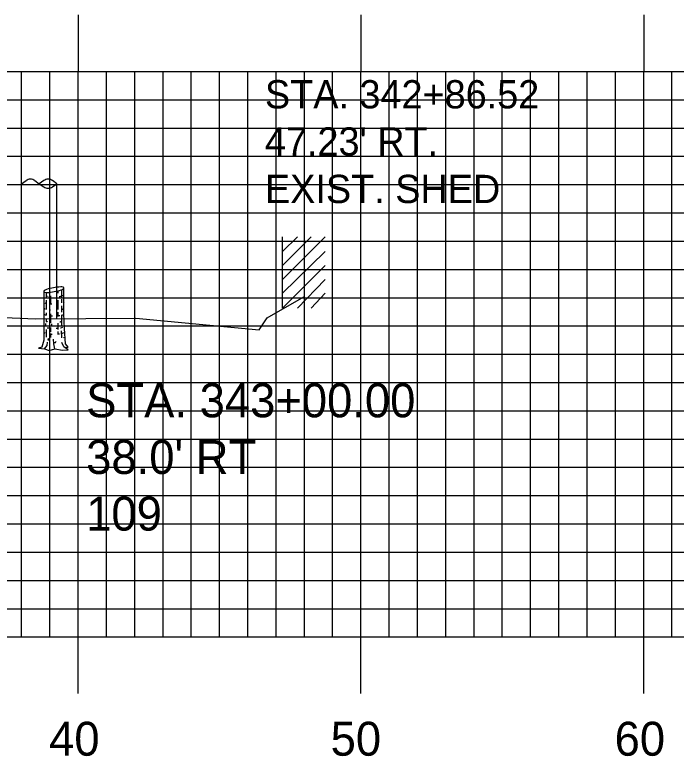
# Model space of a CAD drawing. Extents: x 1825147 to 1825490, y 442591 to 442811.
# Drawn here: x 1825350.12 to 1825373.51, y 442684.45 to 442710.67 of the extents above; entities that cross this region are included whole.
import ezdxf

# ---------------------------------------------------------------- set-up
doc = ezdxf.new("R2010")
doc.units = 0
for name, color, linetype in [('D_Drainage_Text', 7, 'Continuous'), ('D_Text_Monospaced', 7, 'Continuous'), ('D_Utilities_Pole_Joint', 7, 'Continuous'), ('H_V ANNOTATION', 7, 'Continuous'), ('MAJOR', 7, 'Continuous'), ('MINOR', 7, 'Continuous'), ('S_Buildings_SillElevation', 7, 'Continuous'), ('S_Roadway_Centerline', 7, 'Continuous'), ('S_Trees_Conifer_NonPay', 7, 'Continuous')]:
    doc.layers.add(name, color=color, linetype=linetype)

msp = doc.modelspace()

# ---------------------------------------------------------------- linework, layer by layer
at = {"layer": 'D_Utilities_Pole_Joint'}
for p, q in [((1825350.361, 442704.693), (1825350.517, 442704.804)), ((1825350.361, 442699.936), (1825350.361, 442704.693)), ((1825350.83, 442704.804), (1825350.986, 442704.693)), ((1825351.142, 442704.804), (1825350.986, 442704.693)), ((1825350.986, 442704.693), (1825351.142, 442704.582)), ((1825351.611, 442704.693), (1825351.455, 442704.804)), ((1825351.455, 442704.582), (1825351.611, 442704.693)), ((1825351.611, 442699.936), (1825351.611, 442704.693))]:
    msp.add_line(p, q, dxfattribs=at)
for centre, start, end in [((1825350.673, 442704.583), 90, 125.2644), ((1825350.673, 442704.583), 54.7356, 90), ((1825351.298, 442704.583), 90, 125.2644), ((1825351.298, 442704.583), 54.7356, 90), ((1825351.298, 442704.804), 234.7356, 270), ((1825351.298, 442704.804), 270, 305.2644)]:
    msp.add_arc(centre, 0.271, start, end, dxfattribs=at)
at = {"layer": 'MAJOR'}
for p, q in [((1825352.361, 442710.669), (1825352.361, 442708.665)), ((1825362.361, 442710.669), (1825362.361, 442708.665)), ((1825372.361, 442710.669), (1825372.361, 442708.665)), ((1825172.361, 442708.665), (1825452.361, 442708.665)), ((1825172.361, 442708.665), (1825452.361, 442708.665)), ((1825172.361, 442708.665), (1825452.361, 442708.665)), ((1825352.361, 442688.665), (1825352.361, 442708.665)), ((1825352.361, 442688.665), (1825352.361, 442708.665)), ((1825362.361, 442688.665), (1825362.361, 442708.665)), ((1825362.361, 442688.665), (1825362.361, 442708.665)), ((1825372.361, 442688.665), (1825372.361, 442708.665)), ((1825372.361, 442688.665), (1825372.361, 442708.665)), ((1825172.361, 442703.665), (1825452.361, 442703.665)), ((1825172.361, 442703.665), (1825452.361, 442703.665)), ((1825172.361, 442698.665), (1825452.361, 442698.665)), ((1825172.361, 442698.665), (1825452.361, 442698.665)), ((1825172.361, 442693.665), (1825452.361, 442693.665)), ((1825172.361, 442693.665), (1825452.361, 442693.665)), ((1825172.361, 442688.665), (1825452.361, 442688.665)), ((1825172.361, 442688.665), (1825452.361, 442688.665)), ((1825172.361, 442688.665), (1825452.361, 442688.665)), ((1825352.361, 442686.661), (1825352.361, 442688.665)), ((1825362.361, 442686.661), (1825362.361, 442688.665)), ((1825372.361, 442686.661), (1825372.361, 442688.665))]:
    msp.add_line(p, q, dxfattribs=at)
at = {"layer": 'MINOR'}
for p, q in [((1825350.361, 442688.665), (1825350.361, 442708.665)), ((1825350.361, 442688.665), (1825350.361, 442708.665)), ((1825351.361, 442688.665), (1825351.361, 442708.665)), ((1825351.361, 442688.665), (1825351.361, 442708.665)), ((1825353.361, 442688.665), (1825353.361, 442708.665)), ((1825353.361, 442688.665), (1825353.361, 442708.665)), ((1825354.361, 442688.665), (1825354.361, 442708.665)), ((1825354.361, 442688.665), (1825354.361, 442708.665)), ((1825355.361, 442688.665), (1825355.361, 442708.665)), ((1825355.361, 442688.665), (1825355.361, 442708.665)), ((1825356.361, 442688.665), (1825356.361, 442708.665)), ((1825356.361, 442688.665), (1825356.361, 442708.665)), ((1825357.361, 442688.665), (1825357.361, 442708.665)), ((1825357.361, 442688.665), (1825357.361, 442708.665)), ((1825358.361, 442688.665), (1825358.361, 442708.665)), ((1825358.361, 442688.665), (1825358.361, 442708.665)), ((1825359.361, 442688.665), (1825359.361, 442708.665)), ((1825359.361, 442688.665), (1825359.361, 442708.665)), ((1825360.361, 442688.665), (1825360.361, 442708.665)), ((1825360.361, 442688.665), (1825360.361, 442708.665)), ((1825361.361, 442688.665), (1825361.361, 442708.665)), ((1825361.361, 442688.665), (1825361.361, 442708.665)), ((1825363.361, 442688.665), (1825363.361, 442708.665)), ((1825363.361, 442688.665), (1825363.361, 442708.665)), ((1825364.361, 442688.665), (1825364.361, 442708.665)), ((1825364.361, 442688.665), (1825364.361, 442708.665)), ((1825365.361, 442688.665), (1825365.361, 442708.665)), ((1825365.361, 442688.665), (1825365.361, 442708.665)), ((1825366.361, 442688.665), (1825366.361, 442708.665)), ((1825366.361, 442688.665), (1825366.361, 442708.665)), ((1825367.361, 442688.665), (1825367.361, 442708.665)), ((1825367.361, 442688.665), (1825367.361, 442708.665)), ((1825368.361, 442688.665), (1825368.361, 442708.665)), ((1825368.361, 442688.665), (1825368.361, 442708.665)), ((1825369.361, 442688.665), (1825369.361, 442708.665)), ((1825369.361, 442688.665), (1825369.361, 442708.665)), ((1825370.361, 442688.665), (1825370.361, 442708.665)), ((1825370.361, 442688.665), (1825370.361, 442708.665)), ((1825371.361, 442688.665), (1825371.361, 442708.665)), ((1825371.361, 442688.665), (1825371.361, 442708.665)), ((1825373.361, 442688.665), (1825373.361, 442708.665)), ((1825373.361, 442688.665), (1825373.361, 442708.665)), ((1825172.361, 442707.665), (1825452.361, 442707.665)), ((1825172.361, 442707.665), (1825452.361, 442707.665)), ((1825172.361, 442706.665), (1825452.361, 442706.665)), ((1825172.361, 442706.665), (1825452.361, 442706.665)), ((1825172.361, 442705.665), (1825452.361, 442705.665)), ((1825172.361, 442705.665), (1825452.361, 442705.665)), ((1825172.361, 442704.665), (1825452.361, 442704.665)), ((1825172.361, 442704.665), (1825452.361, 442704.665)), ((1825172.361, 442702.665), (1825452.361, 442702.665)), ((1825172.361, 442702.665), (1825452.361, 442702.665)), ((1825172.361, 442701.665), (1825452.361, 442701.665)), ((1825172.361, 442701.665), (1825452.361, 442701.665)), ((1825172.361, 442700.665), (1825452.361, 442700.665)), ((1825172.361, 442700.665), (1825452.361, 442700.665)), ((1825172.361, 442699.665), (1825452.361, 442699.665)), ((1825172.361, 442699.665), (1825452.361, 442699.665)), ((1825172.361, 442697.665), (1825452.361, 442697.665)), ((1825172.361, 442697.665), (1825452.361, 442697.665)), ((1825172.361, 442696.665), (1825452.361, 442696.665)), ((1825172.361, 442696.665), (1825452.361, 442696.665)), ((1825172.361, 442695.665), (1825452.361, 442695.665)), ((1825172.361, 442695.665), (1825452.361, 442695.665)), ((1825172.361, 442694.665), (1825452.361, 442694.665)), ((1825172.361, 442694.665), (1825452.361, 442694.665)), ((1825172.361, 442692.665), (1825452.361, 442692.665)), ((1825172.361, 442692.665), (1825452.361, 442692.665)), ((1825172.361, 442691.665), (1825452.361, 442691.665)), ((1825172.361, 442691.665), (1825452.361, 442691.665)), ((1825172.361, 442690.665), (1825452.361, 442690.665)), ((1825172.361, 442690.665), (1825452.361, 442690.665)), ((1825172.361, 442689.665), (1825452.361, 442689.665)), ((1825172.361, 442689.665), (1825452.361, 442689.665))]:
    msp.add_line(p, q, dxfattribs=at)
at = {"layer": 'S_Buildings_SillElevation'}
for p, q in [((1825359.588, 442700.296), (1825359.588, 442702.822)), ((1825359.588, 442701.313), (1825361.098, 442702.822)), ((1825359.588, 442701.805), (1825360.605, 442702.822)), ((1825359.588, 442702.297), (1825360.113, 442702.822)), ((1825359.588, 442700.821), (1825361.098, 442702.297)), ((1825359.588, 442700.296), (1825361.098, 442701.805)), ((1825360.113, 442700.296), (1825361.098, 442701.313)), ((1825360.605, 442700.296), (1825361.098, 442700.821))]:
    msp.add_line(p, q, dxfattribs=at)
at = {"layer": 'S_Roadway_Centerline'}
msp.add_lwpolyline([(1825324.751, 442702.284), (1825326.279, 442702.169), (1825329.368, 442702.108), (1825331.382, 442702.082), (1825331.777, 442702.121), (1825333.735, 442702.064), (1825334.12, 442702.1), (1825338.877, 442701.185), (1825339.617, 442701.17), (1825339.689, 442701.142), (1825340.614, 442701.071), (1825343.489, 442700.583), (1825346.64, 442700.125), (1825347.777, 442700.042), (1825350.864, 442699.915), (1825354.395, 442699.942), (1825358.764, 442699.53), (1825359.047, 442699.947), (1825360.34, 442700.695)], dxfattribs=at)
at = {"layer": 'S_Trees_Conifer_NonPay'}
for p, q in [((1825351.224, 442700.85), (1825351.224, 442700.645)), ((1825351.381, 442700.725), (1825351.381, 442700.452)), ((1825351.642, 442700.905), (1825351.642, 442700.827)), ((1825351.224, 442700.572), (1825351.224, 442700.241)), ((1825351.642, 442700.577), (1825351.642, 442700.252)), ((1825351.777, 442700.617), (1825351.777, 442700.486)), ((1825351.777, 442700.377), (1825351.777, 442700.151)), ((1825351.224, 442700.126), (1825351.224, 442700.048)), ((1825351.224, 442699.933), (1825351.224, 442699.824)), ((1825351.381, 442700.098), (1825351.381, 442699.78)), ((1825351.642, 442700.151), (1825351.642, 442699.997)), ((1825351.777, 442700.059), (1825351.777, 442699.683)), ((1825351.207, 442699.746), (1825351.207, 442699.649)), ((1825351.422, 442699.735), (1825351.422, 442699.666)), ((1825351.642, 442699.769), (1825351.642, 442699.535)), ((1825351.224, 442699.535), (1825351.224, 442699.267)), ((1825351.381, 442699.61), (1825351.381, 442699.451)), ((1825351.642, 442699.473), (1825351.642, 442699.387)), ((1825351.759, 442699.49), (1825351.776, 442699.244)), ((1825351.381, 442699.393), (1825351.381, 442699.262)), ((1825351.837, 442699.262), (1825351.898, 442699.268))]:
    msp.add_line(p, q, dxfattribs=at)
for points in [[(1825351.888, 442698.901), (1825352.004, 442698.91), (1825351.912, 442699.035), (1825351.879, 442699.576), (1825351.858, 442700.093), (1825351.858, 442701.012)], [(1825351.145, 442700.884), (1825351.145, 442699.166), (1825351.075, 442698.91), (1825350.956, 442698.876), (1825351.173, 442698.859), (1825351.332, 442698.801), (1825351.541, 442698.859), (1825351.804, 442698.812), (1825352.01, 442698.818), (1825351.858, 442698.921), (1825351.787, 442699.075)], [(1825351.777, 442700.946), (1825351.777, 442700.849), (1825351.777, 442700.684)], [(1825351.304, 442699.222), (1825351.293, 442699.178), (1825351.343, 442699.166), (1825351.343, 442699.228)], [(1825351.541, 442698.859), (1825351.497, 442699.035), (1825351.491, 442699.2)], [(1825351.173, 442698.859), (1825351.262, 442698.972), (1825351.28, 442699.086)], [(1825351.495, 442699.085), (1825351.564, 442699.08), (1825351.583, 442699.132)]]:
    msp.add_lwpolyline(points, dxfattribs=at)
for centre, radius, start, end in [((1825351.818, 442699.222), 1.825, 100.3798, 108.3946), ((1825351.818, 442699.222), 1.825, 92.3651, 100.3798), ((1825351.752, 442700.801), 0.245, 70.3798, 92.3651), ((1825351.684, 442701.173), 0.245, 288.3946, 310.3798), ((1825351.81, 442700.963), 0.0729, 59.1402, 70.3798), ((1825351.796, 442701.042), 0.0729, 310.3798, 321.6195), ((1825351.834, 442701.003), 0.0263, 40.3798, 59.1402), ((1825351.832, 442701.013), 0.0263, 321.6195, 340.3798), ((1825351.84, 442701.008), 0.0186, 26.433, 40.3798), ((1825351.844, 442701.01), 0.0141, 10.3798, 26.433), ((1825351.84, 442701.01), 0.0186, 340.3798, 354.3267), ((1825351.844, 442701.01), 0.0141, 354.3267, 10.3798), ((1825351.164, 442700.884), 0.0186, 160.3798, 174.3267), ((1825351.159, 442700.884), 0.0141, 174.3267, 190.3798), ((1825351.159, 442700.884), 0.0141, 190.3798, 206.433), ((1825351.16, 442700.769), 0.0143, 180, 196.0515), ((1825351.171, 442700.881), 0.0263, 141.6195, 160.3798), ((1825351.163, 442700.886), 0.0186, 206.433, 220.3798), ((1825351.169, 442700.891), 0.0263, 220.3798, 239.1402), ((1825351.207, 442700.852), 0.0729, 130.3798, 141.6195), ((1825351.193, 442700.931), 0.0729, 239.1402, 250.3798), ((1825351.319, 442700.721), 0.245, 108.3946, 130.3798), ((1825351.251, 442701.094), 0.245, 250.3798, 272.3651), ((1825351.287, 442700.957), 0.245, 254.8461, 261.8968), ((1825351.185, 442702.673), 1.825, 272.3651, 280.3798), ((1825351.185, 442702.673), 1.825, 280.3798, 288.3946), ((1825351.717, 442700.957), 0.245, 278.1032, 284.1859), ((1825351.717, 442700.957), 0.245, 291.7653, 300), ((1825351.802, 442700.809), 0.0738, 300, 311.2506), ((1825351.833, 442700.774), 0.0267, 311.2506, 330), ((1825351.84, 442700.77), 0.0189, 330, 343.9485), ((1825351.289, 442700.705), 0.245, 244.3148, 257.5375), ((1825351.502, 442702.465), 1.767, 261.8968, 262.605), ((1825351.502, 442702.465), 1.767, 264.3267, 266.0499), ((1825351.502, 442702.465), 1.767, 276.2449, 278.1032), ((1825351.835, 442700.522), 0.0267, 311.2506, 330), ((1825351.842, 442700.518), 0.0189, 330, 343.9485), ((1825351.16, 442700.303), 0.0143, 180, 196.0515), ((1825351.164, 442700.304), 0.0189, 196.0515, 210), ((1825351.171, 442700.308), 0.0267, 210, 228.7494), ((1825351.202, 442700.343), 0.0738, 228.7494, 240), ((1825351.287, 442700.491), 0.245, 240, 246.7914), ((1825351.287, 442700.491), 0.245, 254.8461, 257.5454), ((1825351.502, 442701.999), 1.767, 265.2285, 266.1325), ((1825351.504, 442702.212), 1.767, 265.8991, 267.5962), ((1825351.504, 442702.212), 1.767, 272.7221, 274.4847), ((1825351.717, 442700.491), 0.245, 284.1859, 300), ((1825351.802, 442700.343), 0.0738, 300, 311.2506), ((1825351.833, 442700.308), 0.0267, 311.2506, 330), ((1825351.84, 442700.304), 0.0189, 330, 343.9485), ((1825351.16, 442700.091), 0.0143, 180, 196.0515), ((1825351.164, 442700.092), 0.0189, 196.0515, 210), ((1825351.171, 442700.096), 0.0267, 210, 228.7494), ((1825351.202, 442700.132), 0.0738, 228.7494, 240), ((1825351.288, 442700.28), 0.245, 240, 254.9514), ((1825351.502, 442701.787), 1.767, 266.0429, 268.5525), ((1825351.502, 442701.787), 1.767, 274.5361, 277.0026), ((1825351.717, 442700.28), 0.245, 292.1924, 300), ((1825351.802, 442700.132), 0.0738, 300, 311.2506), ((1825351.833, 442700.096), 0.0267, 311.2506, 330), ((1825351.84, 442700.092), 0.0189, 330, 343.9485), ((1825351.287, 442700.06), 0.245, 254.9814, 261.8968), ((1825351.502, 442701.568), 1.767, 261.8968, 262.45), ((1825351.502, 442701.568), 1.767, 276.7966, 278.1032), ((1825351.716, 442700.06), 0.245, 278.1032, 284.3207), ((1825351.159, 442699.449), 0.0143, 180, 196.0515), ((1825351.159, 442699.655), 0.0143, 180, 196.0515), ((1825351.163, 442699.45), 0.0189, 196.0515, 210), ((1825351.17, 442699.454), 0.0267, 210, 228.7494), ((1825351.201, 442699.49), 0.0738, 228.7494, 240), ((1825351.286, 442699.637), 0.245, 240, 249.1675), ((1825351.502, 442701.351), 1.767, 262.2622, 265.0496), ((1825351.502, 442701.351), 1.767, 272.6293, 274.5612), ((1825351.502, 442701.351), 1.767, 277.63, 278.1032), ((1825351.716, 442699.843), 0.245, 278.1032, 294.6056), ((1825351.716, 442699.637), 0.245, 284.0684, 300), ((1825351.801, 442699.49), 0.0738, 300, 302.05), ((1825351.501, 442701.145), 1.767, 266.0862, 268.2187), ((1825351.501, 442701.145), 1.767, 274.2776, 276.3006)]:
    msp.add_arc(centre, radius, start, end, dxfattribs=at)

# ---------------------------------------------------------------- texts
at = {"layer": 'D_Drainage_Text'}
for s, p in [('STA. 343+00.00', (1825352.644, 442696.434)), ("38.0' RT", (1825352.644, 442694.43)), ('109', (1825352.644, 442692.426))]:
    msp.add_text(s, height=1.2, dxfattribs=at).set_placement(p)
at = {"layer": 'D_Text_Monospaced'}
for s, height, p in [('STA. 342+86.52', 0.99996, (1825358.966, 442707.359)), ("47.23' RT.", 1, (1825358.966, 442705.691)), ('EXIST. SHED', 0.99996, (1825358.966, 442704.011))]:
    msp.add_text(s, height=height, dxfattribs=at).set_placement(p)
at = {"layer": 'H_V ANNOTATION'}
for s, p in [('40', (1825351.333, 442684.465)), ('50', (1825361.29, 442684.465)), ('60', (1825371.333, 442684.465))]:
    msp.add_text(s, height=1.2, dxfattribs=at).set_placement(p)

doc.saveas('drawing.dxf')
